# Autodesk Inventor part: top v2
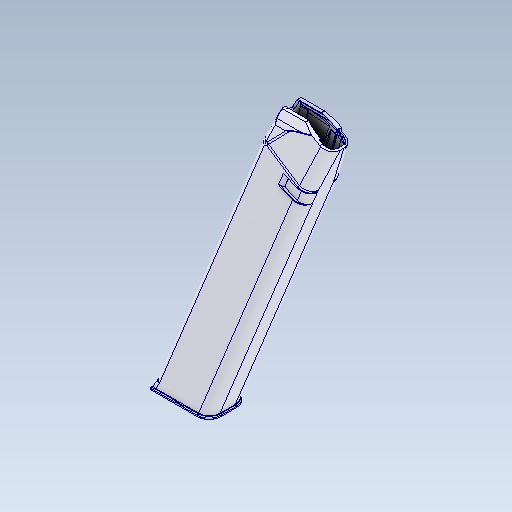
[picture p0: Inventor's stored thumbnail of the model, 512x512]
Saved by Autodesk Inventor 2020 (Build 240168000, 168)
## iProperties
Created: 2019-09
Part Number: top v2
Material: Steel
Document SubType Name: Modeling
Designer: johne
Density: 7.85 g/cm^3
Appearance: Default
Author: johne
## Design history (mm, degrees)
feature "Body1"
body "Solid1"
